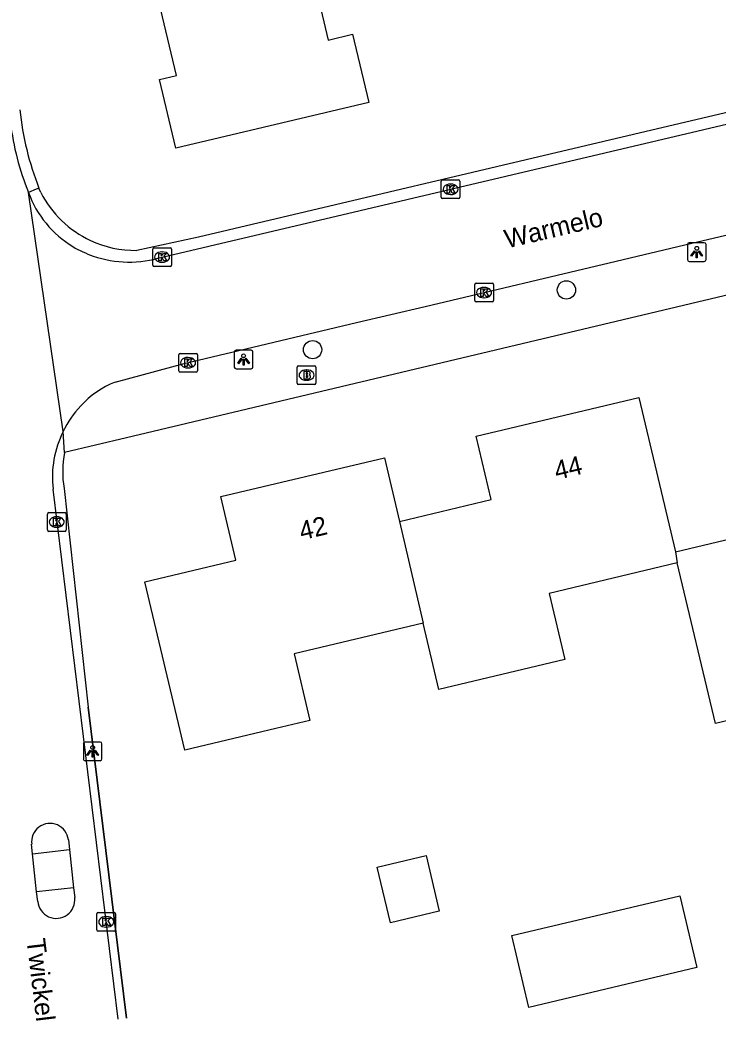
# Model space of a CAD drawing. Extents: x 157663 to 158496, y 379212 to 380934.
# Drawn here: x 158091.9 to 158129.3, y 380411.1 to 380464.5 of the extents above; entities that cross this region are included whole.
import ezdxf

# ---------------------------------------------------------------- set-up
doc = ezdxf.new("R2010")
doc.units = 0
for name, color, linetype in [('IMGEO_Boom', 7, 'Continuous'), ('IMGEO_Brandkraan', 7, 'Continuous'), ('IMGEO_Hek', 7, 'Continuous'), ('IMGEO_Kolk', 7, 'Continuous'), ('IMGEO_Lichtpunt', 7, 'Continuous'), ('IMGEO_Openbare_ruimte_label', 7, 'Continuous'), ('IMGEO_Pand', 7, 'Continuous'), ('IMGEO_Pand_nummerreeks', 7, 'Continuous'), ('IMGEO_Rijbaan_lokaal_open', 7, 'Continuous'), ('IMGEO_Voetpad_open', 7, 'Continuous')]:
    doc.layers.add(name, color=color, linetype=linetype)

msp = doc.modelspace()

# ---------------------------------------------------------------- linework, layer by layer
at = {"layer": 'IMGEO_Boom'}
for centre in [(158121.179, 380450.024), (158107.593, 380446.83)]:
    msp.add_circle(centre, 0.489, dxfattribs=at)
at = {"layer": 'IMGEO_Brandkraan'}
for p, q in [((158106.769, 380445.043), (158106.769, 380445.895)), ((158106.844, 380445.969), (158107.696, 380445.969)), ((158107.257, 380445.749), (158107.282, 380445.749)), ((158107.77, 380445.895), (158107.77, 380445.043)), ((158107.696, 380444.969), (158106.844, 380444.969)), ((158107.28, 380445.189), (158107.255, 380445.189))]:
    msp.add_line(p, q, dxfattribs=at)
for points in [[(158106.769, 380445.043), (158106.769, 380445.895)], [(158106.844, 380445.969), (158107.696, 380445.969)], [(158107.117, 380445.669), (158107.117, 380445.269), (158107.33, 380445.269)], [(158107.348, 380445.669), (158107.117, 380445.669)], [(158107.296, 380445.588), (158107.242, 380445.588), (158107.242, 380445.512)], [(158107.242, 380445.512), (158107.295, 380445.512)], [(158107.77, 380445.895), (158107.77, 380445.043)], [(158107.696, 380444.969), (158106.844, 380444.969)], [(158107.304, 380445.436), (158107.242, 380445.436), (158107.242, 380445.355)], [(158107.242, 380445.355), (158107.304, 380445.355)]]:
    msp.add_lwpolyline(points, dxfattribs=at)
for centre, radius, start, end in [((158106.846, 380445.893), 0.0765, 91.552, 178.448), ((158106.846, 380445.893), 0.0765, 91.552, 178.448), ((158107.297, 380445.55), 0.0379, 267.8285, 90.9355), ((158107.352, 380445.524), 0.145, 59.4692, 91.5367), ((158107.377, 380445.571), 0.0922, 285.5137, 58.1501), ((158107.382, 380445.379), 0.105, 301.3115, 78.989), ((158107.694, 380445.893), 0.0765, 1.552, 88.448), ((158107.694, 380445.893), 0.0765, 1.552, 88.448), ((158106.846, 380445.045), 0.0765, 181.552, 268.448), ((158106.846, 380445.045), 0.0765, 181.552, 268.448), ((158107.305, 380445.395), 0.0404, 269.8759, 90.5077), ((158107.336, 380445.52), 0.251, 268.6676, 293.5347), ((158107.694, 380445.045), 0.0765, 271.552, 358.448), ((158107.694, 380445.045), 0.0765, 271.552, 358.448)]:
    msp.add_arc(centre, radius, start, end, dxfattribs=at)
for centre, major_axis, ratio, start_param, end_param in [((158107.256, 380445.469), (-0.387, 0.002), 0.722429, 4.712389, 7.853982), ((158107.281, 380445.469), (-0.39, 0.002), 0.717154, 1.570796, 4.712389)]:
    msp.add_ellipse(centre, major_axis=major_axis, ratio=ratio, start_param=start_param, end_param=end_param, dxfattribs=at)
at = {"layer": 'IMGEO_Hek'}
for points in [[(158124.778, 380458.345), (158101.496, 380452.845)], [(158097.636, 380411.068), (158095.577, 380427.704)]]:
    msp.add_lwpolyline(points, dxfattribs=at)
at = {"layer": 'IMGEO_Kolk'}
for p, q in [((158114.478, 380454.98), (158114.478, 380455.832)), ((158114.553, 380455.906), (158115.405, 380455.906)), ((158114.966, 380455.686), (158114.991, 380455.686)), ((158115.479, 380455.832), (158115.479, 380454.98)), ((158114.989, 380455.126), (158114.964, 380455.126)), ((158115.405, 380454.906), (158114.553, 380454.906)), ((158099.04, 380451.354), (158099.04, 380452.206)), ((158099.115, 380452.28), (158099.967, 380452.28)), ((158099.528, 380452.06), (158099.553, 380452.06)), ((158100.041, 380452.206), (158100.041, 380451.354)), ((158099.551, 380451.5), (158099.526, 380451.5)), ((158099.967, 380451.28), (158099.115, 380451.28)), ((158116.273, 380449.454), (158116.273, 380450.306)), ((158116.348, 380450.38), (158117.2, 380450.38)), ((158117.274, 380450.306), (158117.274, 380449.454)), ((158116.761, 380450.16), (158116.786, 380450.16)), ((158117.2, 380449.38), (158116.348, 380449.38)), ((158116.784, 380449.6), (158116.759, 380449.6)), ((158100.43, 380445.704), (158100.43, 380446.556)), ((158100.505, 380446.63), (158101.357, 380446.63)), ((158101.431, 380446.556), (158101.431, 380445.704)), ((158100.918, 380446.41), (158100.943, 380446.41)), ((158101.357, 380445.63), (158100.505, 380445.63)), ((158100.941, 380445.85), (158100.916, 380445.85)), ((158093.4, 380437.185), (158093.4, 380438.037)), ((158093.475, 380438.111), (158094.327, 380438.111)), ((158094.401, 380438.037), (158094.401, 380437.185)), ((158093.888, 380437.891), (158093.913, 380437.891)), ((158094.327, 380437.111), (158093.475, 380437.111)), ((158093.911, 380437.331), (158093.886, 380437.331)), ((158096.047, 380415.798), (158096.047, 380416.65)), ((158096.122, 380416.724), (158096.974, 380416.724)), ((158097.048, 380416.65), (158097.048, 380415.798)), ((158096.535, 380416.504), (158096.56, 380416.504)), ((158096.974, 380415.724), (158096.122, 380415.724)), ((158096.558, 380415.944), (158096.533, 380415.944))]:
    msp.add_line(p, q, dxfattribs=at)
for points in [[(158114.478, 380454.98), (158114.478, 380455.832)], [(158114.553, 380455.906), (158115.405, 380455.906)], [(158114.799, 380455.606), (158114.922, 380455.606), (158114.922, 380455.455), (158115.052, 380455.606), (158115.216, 380455.606), (158115.07, 380455.455), (158115.223, 380455.206), (158115.071, 380455.206), (158114.986, 380455.37), (158114.922, 380455.303), (158114.922, 380455.206), (158114.799, 380455.206), (158114.799, 380455.606)], [(158115.479, 380455.832), (158115.479, 380454.98)], [(158115.405, 380454.906), (158114.553, 380454.906)], [(158099.04, 380451.354), (158099.04, 380452.206)], [(158099.115, 380452.28), (158099.967, 380452.28)], [(158099.361, 380451.98), (158099.484, 380451.98), (158099.484, 380451.829), (158099.614, 380451.98), (158099.778, 380451.98), (158099.632, 380451.829), (158099.785, 380451.58), (158099.633, 380451.58), (158099.548, 380451.744), (158099.484, 380451.677), (158099.484, 380451.58), (158099.361, 380451.58), (158099.361, 380451.98)], [(158100.041, 380452.206), (158100.041, 380451.354)], [(158099.967, 380451.28), (158099.115, 380451.28)], [(158116.273, 380449.454), (158116.273, 380450.306)], [(158116.348, 380450.38), (158117.2, 380450.38)], [(158117.274, 380450.306), (158117.274, 380449.454)], [(158116.594, 380450.08), (158116.717, 380450.08), (158116.717, 380449.929), (158116.847, 380450.08), (158117.011, 380450.08), (158116.865, 380449.929), (158117.018, 380449.68), (158116.866, 380449.68), (158116.781, 380449.844), (158116.717, 380449.777), (158116.717, 380449.68), (158116.594, 380449.68), (158116.594, 380450.08)], [(158117.2, 380449.38), (158116.348, 380449.38)], [(158100.43, 380445.704), (158100.43, 380446.556)], [(158100.505, 380446.63), (158101.357, 380446.63)], [(158101.431, 380446.556), (158101.431, 380445.704)], [(158100.751, 380446.33), (158100.874, 380446.33), (158100.874, 380446.179), (158101.004, 380446.33), (158101.168, 380446.33), (158101.022, 380446.179), (158101.175, 380445.93), (158101.023, 380445.93), (158100.938, 380446.094), (158100.874, 380446.027), (158100.874, 380445.93), (158100.751, 380445.93), (158100.751, 380446.33)], [(158101.357, 380445.63), (158100.505, 380445.63)], [(158093.4, 380437.185), (158093.4, 380438.037)], [(158093.475, 380438.111), (158094.327, 380438.111)], [(158094.401, 380438.037), (158094.401, 380437.185)], [(158093.721, 380437.811), (158093.844, 380437.811), (158093.844, 380437.66), (158093.974, 380437.811), (158094.138, 380437.811), (158093.992, 380437.66), (158094.145, 380437.411), (158093.993, 380437.411), (158093.908, 380437.575), (158093.844, 380437.508), (158093.844, 380437.411), (158093.721, 380437.411), (158093.721, 380437.811)], [(158094.327, 380437.111), (158093.475, 380437.111)], [(158096.047, 380415.798), (158096.047, 380416.65)], [(158096.122, 380416.724), (158096.974, 380416.724)], [(158097.048, 380416.65), (158097.048, 380415.798)], [(158096.368, 380416.424), (158096.491, 380416.424), (158096.491, 380416.273), (158096.621, 380416.424), (158096.785, 380416.424), (158096.639, 380416.273), (158096.792, 380416.024), (158096.64, 380416.024), (158096.555, 380416.188), (158096.491, 380416.121), (158096.491, 380416.024), (158096.368, 380416.024), (158096.368, 380416.424)], [(158096.974, 380415.724), (158096.122, 380415.724)]]:
    msp.add_lwpolyline(points, dxfattribs=at)
for centre, start, end in [((158114.555, 380455.83), 91.552, 178.448), ((158114.555, 380455.83), 91.552, 178.448), ((158115.403, 380455.83), 1.552, 88.448), ((158115.403, 380455.83), 1.552, 88.448), ((158114.555, 380454.982), 181.552, 268.448), ((158114.555, 380454.982), 181.552, 268.448), ((158115.403, 380454.982), 271.552, 358.448), ((158115.403, 380454.982), 271.552, 358.448), ((158099.117, 380452.204), 91.552, 178.448), ((158099.117, 380452.204), 91.552, 178.448), ((158099.965, 380452.204), 1.552, 88.448), ((158099.965, 380452.204), 1.552, 88.448), ((158099.117, 380451.356), 181.552, 268.448), ((158099.117, 380451.356), 181.552, 268.448), ((158099.965, 380451.356), 271.552, 358.448), ((158099.965, 380451.356), 271.552, 358.448), ((158116.35, 380450.304), 91.552, 178.448), ((158116.35, 380450.304), 91.552, 178.448), ((158117.198, 380450.304), 1.552, 88.448), ((158117.198, 380450.304), 1.552, 88.448), ((158116.35, 380449.456), 181.552, 268.448), ((158116.35, 380449.456), 181.552, 268.448), ((158117.198, 380449.456), 271.552, 358.448), ((158117.198, 380449.456), 271.552, 358.448), ((158100.507, 380446.554), 91.552, 178.448), ((158100.507, 380446.554), 91.552, 178.448), ((158101.355, 380446.554), 1.552, 88.448), ((158101.355, 380446.554), 1.552, 88.448), ((158100.507, 380445.706), 181.552, 268.448), ((158100.507, 380445.706), 181.552, 268.448), ((158101.355, 380445.706), 271.552, 358.448), ((158101.355, 380445.706), 271.552, 358.448), ((158093.477, 380438.035), 91.552, 178.448), ((158093.477, 380438.035), 91.552, 178.448), ((158094.325, 380438.035), 1.552, 88.448), ((158094.325, 380438.035), 1.552, 88.448), ((158093.477, 380437.187), 181.552, 268.448), ((158093.477, 380437.187), 181.552, 268.448), ((158094.325, 380437.187), 271.552, 358.448), ((158094.325, 380437.187), 271.552, 358.448), ((158096.124, 380416.648), 91.552, 178.448), ((158096.124, 380416.648), 91.552, 178.448), ((158096.972, 380416.648), 1.552, 88.448), ((158096.972, 380416.648), 1.552, 88.448), ((158096.124, 380415.8), 181.552, 268.448), ((158096.124, 380415.8), 181.552, 268.448), ((158096.972, 380415.8), 271.552, 358.448), ((158096.972, 380415.8), 271.552, 358.448)]:
    msp.add_arc(centre, 0.0765, start, end, dxfattribs=at)
for centre, major_axis, ratio, start_param, end_param in [((158114.965, 380455.406), (-0.387, 0.002), 0.722429, 4.712389, 7.853982), ((158114.99, 380455.406), (-0.39, 0.002), 0.717154, 1.570796, 4.712389), ((158099.527, 380451.78), (-0.387, 0.002), 0.722429, 4.712389, 7.853982), ((158099.552, 380451.78), (-0.39, 0.002), 0.717154, 1.570796, 4.712389), ((158116.76, 380449.88), (-0.387, 0.002), 0.722429, 4.712389, 7.853982), ((158116.785, 380449.88), (-0.39, 0.002), 0.717154, 1.570796, 4.712389), ((158100.917, 380446.13), (-0.387, 0.002), 0.722429, 4.712389, 7.853982), ((158100.942, 380446.13), (-0.39, 0.002), 0.717154, 1.570796, 4.712389), ((158093.887, 380437.611), (-0.387, 0.002), 0.722429, 4.712389, 7.853982), ((158093.912, 380437.611), (-0.39, 0.002), 0.717154, 1.570796, 4.712389), ((158096.534, 380416.224), (-0.387, 0.002), 0.722429, 4.712389, 7.853982), ((158096.559, 380416.224), (-0.39, 0.002), 0.717154, 1.570796, 4.712389)]:
    msp.add_ellipse(centre, major_axis=major_axis, ratio=ratio, start_param=start_param, end_param=end_param, dxfattribs=at)
at = {"layer": 'IMGEO_Lichtpunt'}
for p, q in [((158127.656, 380452.451), (158127.656, 380451.644)), ((158127.656, 380452.451), (158127.656, 380451.644)), ((158128.558, 380452.546), (158127.75, 380452.546)), ((158128.558, 380452.546), (158127.75, 380452.546)), ((158128.652, 380451.644), (158128.652, 380452.451)), ((158128.652, 380451.644), (158128.652, 380452.451)), ((158127.75, 380451.55), (158128.558, 380451.55)), ((158127.75, 380451.55), (158128.558, 380451.55)), ((158103.403, 380446.705), (158103.403, 380445.898)), ((158103.403, 380446.705), (158103.403, 380445.898)), ((158104.305, 380446.8), (158103.497, 380446.8)), ((158104.305, 380446.8), (158103.497, 380446.8)), ((158104.399, 380445.898), (158104.399, 380446.705)), ((158104.399, 380445.898), (158104.399, 380446.705)), ((158103.497, 380445.804), (158104.305, 380445.804)), ((158103.497, 380445.804), (158104.305, 380445.804)), ((158095.324, 380425.746), (158095.324, 380424.939)), ((158095.324, 380425.746), (158095.324, 380424.939)), ((158096.226, 380425.841), (158095.418, 380425.841)), ((158096.226, 380425.841), (158095.418, 380425.841)), ((158096.32, 380424.939), (158096.32, 380425.746)), ((158096.32, 380424.939), (158096.32, 380425.746)), ((158095.418, 380424.845), (158096.226, 380424.845)), ((158095.418, 380424.845), (158096.226, 380424.845))]:
    msp.add_line(p, q, dxfattribs=at)
for points in [[(158128.03, 380452.115), (158128.069, 380452.087), (158127.881, 380451.825), (158127.843, 380451.852), (158128.03, 380452.115)], [(158128.132, 380452.067), (158128.179, 380452.067), (158128.179, 380451.745), (158128.132, 380451.745), (158128.132, 380452.067)], [(158128.242, 380452.087), (158128.28, 380452.114), (158128.467, 380451.852), (158128.428, 380451.824), (158128.242, 380452.087)], [(158103.777, 380446.369), (158103.816, 380446.341), (158103.628, 380446.079), (158103.59, 380446.106), (158103.777, 380446.369)], [(158103.879, 380446.321), (158103.926, 380446.321), (158103.926, 380445.999), (158103.879, 380445.999), (158103.879, 380446.321)], [(158103.989, 380446.341), (158104.027, 380446.368), (158104.214, 380446.106), (158104.175, 380446.078), (158103.989, 380446.341)], [(158095.698, 380425.41), (158095.737, 380425.382), (158095.549, 380425.12), (158095.511, 380425.147), (158095.698, 380425.41)], [(158095.8, 380425.362), (158095.847, 380425.362), (158095.847, 380425.04), (158095.8, 380425.04), (158095.8, 380425.362)], [(158095.91, 380425.382), (158095.948, 380425.409), (158096.135, 380425.147), (158096.096, 380425.119), (158095.91, 380425.382)]]:
    msp.add_lwpolyline(points, dxfattribs=at)
for centre in [(158128.155, 380452.249), (158103.902, 380446.503), (158095.823, 380425.544)]:
    msp.add_circle(centre, 0.0994, dxfattribs=at)
for centre, start, end in [((158127.75, 380452.451), 90, 180), ((158127.75, 380452.451), 90, 180), ((158128.558, 380452.451), 0, 90), ((158128.558, 380452.451), 0, 90), ((158127.75, 380451.644), 180, 270), ((158127.75, 380451.644), 180, 270), ((158128.558, 380451.644), 270, 0), ((158128.558, 380451.644), 270, 360), ((158103.497, 380446.705), 90, 180), ((158103.497, 380446.705), 90, 180), ((158104.305, 380446.705), 0, 90), ((158104.305, 380446.705), 0, 90), ((158103.497, 380445.898), 180, 270), ((158103.497, 380445.898), 180, 270), ((158104.305, 380445.898), 270, 0), ((158104.305, 380445.898), 270, 360), ((158095.418, 380425.746), 90, 180), ((158095.418, 380425.746), 90, 180), ((158096.226, 380425.746), 0, 90), ((158096.226, 380425.746), 0, 90), ((158095.418, 380424.939), 180, 270), ((158095.418, 380424.939), 180, 270), ((158096.226, 380424.939), 270, 0), ((158096.226, 380424.939), 270, 360)]:
    msp.add_arc(centre, 0.0946, start, end, dxfattribs=at)
at = {"layer": 'IMGEO_Pand'}
for points in [[(158106.156, 380472.982), (158108.425, 380463.389), (158109.731, 380463.698), (158110.596, 380460.042), (158100.273, 380457.601), (158099.402, 380461.283), (158100.307, 380461.497), (158098.997, 380467.037), (158098.025, 380466.807), (158097.078, 380470.812)], [(158112.25, 380437.64), (158117.155, 380438.805), (158116.347, 380442.206), (158125.056, 380444.275), (158127.02, 380436.009)], [(158127.02, 380436.009), (158131.893, 380437.167), (158131.07, 380440.631), (158139.798, 380442.704), (158140.615, 380439.266)], [(158113.508, 380432.199), (158106.6, 380430.558), (158107.448, 380426.991), (158105.625, 380426.558), (158100.76, 380425.402), (158098.619, 380434.412), (158103.483, 380435.568), (158102.675, 380438.967), (158111.44, 380441.049), (158112.25, 380437.64)], [(158112.25, 380437.64), (158113.508, 380432.199)], [(158127.02, 380436.009), (158127.112, 380435.418)], [(158127.112, 380435.418), (158120.252, 380433.788), (158121.093, 380430.248), (158114.352, 380428.646), (158113.508, 380432.199)], [(158141.937, 380433.653), (158135.06, 380432.02), (158135.91, 380428.444), (158129.15, 380426.838), (158127.112, 380435.418)], [(158111.756, 380416.175), (158111.047, 380419.154), (158113.669, 380419.777), (158114.377, 380416.798), (158111.756, 380416.175)], [(158128.165, 380413.773), (158119.166, 380411.635), (158118.252, 380415.485), (158127.251, 380417.623), (158128.165, 380413.773)]]:
    msp.add_lwpolyline(points, dxfattribs=at)
at = {"layer": 'IMGEO_Rijbaan_lokaal_open'}
for points in [[(158099.541, 380451.78), (158152.218, 380464.191)], [(158097.028, 380445.091), (158100.713, 380446.084), (158109.944, 380448.275), (158113.619, 380449.137), (158123.835, 380451.559), (158127.515, 380452.429), (158137.287, 380454.744), (158140.965, 380455.614), (158149.78, 380457.705), (158151.028, 380457.922)], [(158094.236, 380442.447), (158092.385, 380455.237)], [(158097.191, 380411.019), (158093.701, 380439.371)], [(158092.609, 380419.859), (158092.558, 380420.371)], [(158094.521, 380420.602), (158094.586, 380420.087)], [(158092.817, 380417.826), (158092.609, 380419.859)], [(158094.586, 380420.087), (158094.804, 380418.035)], [(158092.892, 380417.319), (158092.817, 380417.826)], [(158094.804, 380418.035), (158094.862, 380417.521)]]:
    msp.add_lwpolyline(points, dxfattribs=at)
for centre, radius, start, end in [((158106.334, 380460.847), 15.035, 187.1492, 201.909), ((158097.674, 380457.156), 5.626, 199.9394, 238.8417), ((158097.764, 380457.378), 5.863, 239.2161, 250.9806), ((158097.781, 380457.413), 5.902, 250.9375, 287.3537), ((158098.858, 380440.441), 4.997, 111.4819, 137.3744), ((158099.305, 380439.984), 5.636, 137.0337, 154.0835), ((158099.297, 380439.982), 5.629, 154.0328, 186.234), ((158093.538, 380420.503), 0.988, 5.7277, 187.6954), ((158093.879, 380417.4), 0.99, 184.7032, 7.0059)]:
    msp.add_arc(centre, radius, start, end, dxfattribs=at)
at = {"layer": 'IMGEO_Voetpad_open'}
for points in [[(158150.758, 380464.463), (158142.265, 380462.453), (158124.778, 380458.345), (158101.496, 380452.845), (158098.183, 380452.136)], [(158092.95, 380455.473), (158092.8, 380455.411), (158092.385, 380455.237)], [(158093.048, 380455.233), (158092.95, 380455.473)], [(158150.8, 380454.739), (158097.631, 380442.115), (158094.318, 380441.328)], [(158094.318, 380441.328), (158094.236, 380442.447)], [(158094.291, 380439.409), (158095.577, 380427.704), (158097.636, 380411.068)], [(158092.609, 380419.859), (158094.586, 380420.087)], [(158094.804, 380418.035), (158092.817, 380417.826)]]:
    msp.add_lwpolyline(points, dxfattribs=at)
for centre, radius, start, end in [((158107.332, 380461.195), 15.479, 185.7315, 201.6945), ((158098.123, 380457.836), 5.703, 207.1507, 244.8502), ((158098.113, 380457.827), 5.691, 244.9002, 270.7025), ((158099.645, 380440.293), 5.427, 169.0092, 189.3786)]:
    msp.add_arc(centre, radius, start, end, dxfattribs=at)

# ---------------------------------------------------------------- texts
at = {"layer": 'IMGEO_Openbare_ruimte_label'}
for s, rotation, p in [('Warmelo', 13.2307, (158117.999, 380452.239)), ('Twickel', 276.8905, (158092.279, 380415.273))]:
    msp.add_text(s, height=1, rotation=rotation, dxfattribs=at).set_placement(p)
at = {"layer": 'IMGEO_Pand_nummerreeks'}
for s, rotation, p in [('44', 13.364, (158120.656, 380439.858)), ('42', 13.3622, (158107.009, 380436.626))]:
    msp.add_text(s, height=1, rotation=rotation, dxfattribs=at).set_placement(p)

doc.saveas('drawing.dxf')
